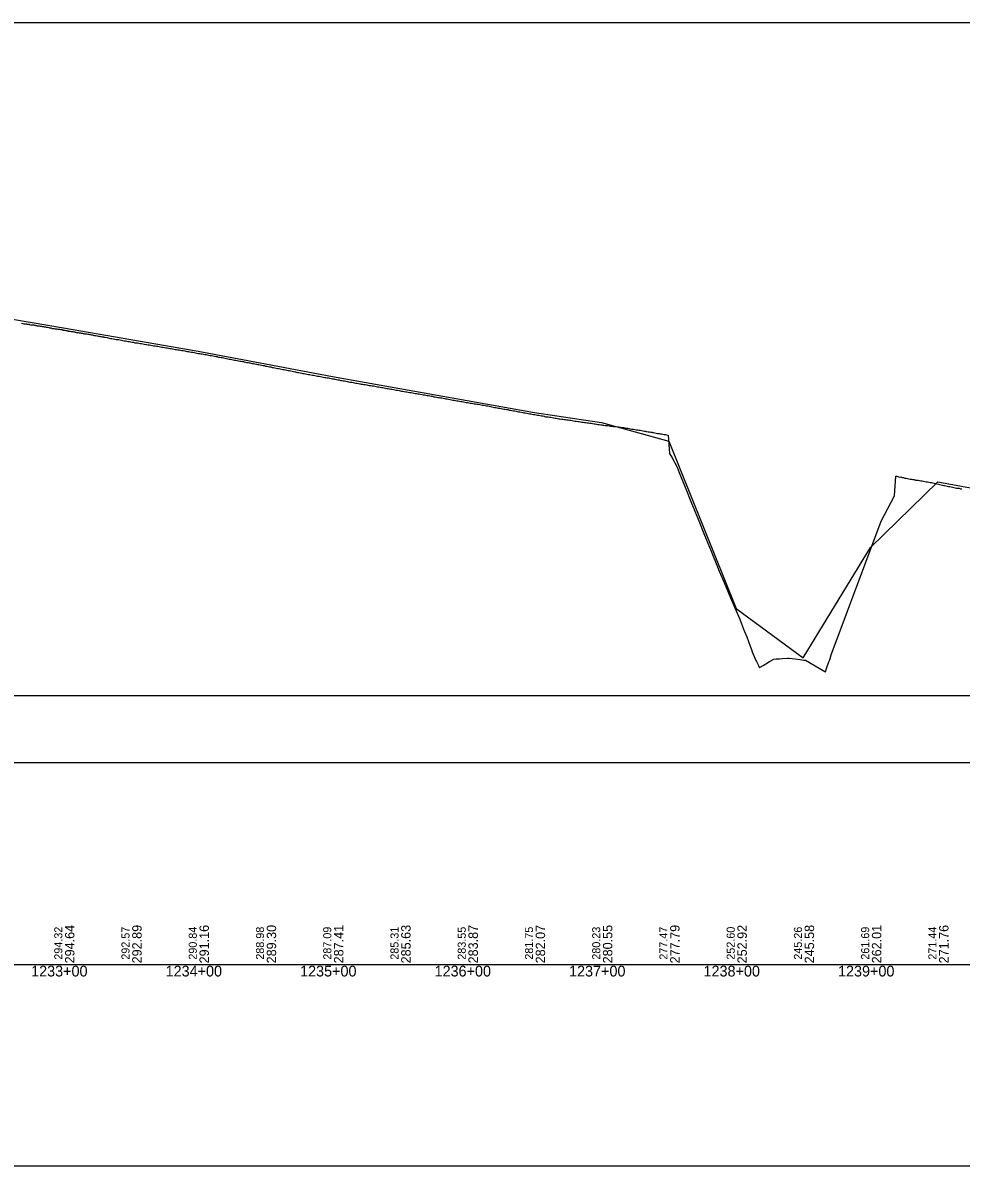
# Model space of a CAD drawing. Extents: x 2898 to 49495, y -15038 to -13538.
# Drawn here: x 12623 to 13321, y -15038 to -14188 of the extents above; entities that cross this region are included whole.
import ezdxf

# ---------------------------------------------------------------- set-up
doc = ezdxf.new("R2010")
doc.units = 0
for name, color, linetype in [('RD_DDB_Profile_EX', 7, 'Continuous'), ('RD_DDB_Profile_PR', 7, 'Continuous'), ('RD_DDB_StaTX', 7, 'Continuous'), ('RD_DDB_StripGrade', 7, 'Continuous'), ('RD_GPK_Profile_Cell', 7, 'Continuous'), ('RD_SHT_ShtClip', 7, 'Continuous')]:
    doc.layers.add(name, color=color, linetype=linetype)

msp = doc.modelspace()

# ---------------------------------------------------------------- linework, layer by layer
at = {"layer": 'RD_DDB_Profile_EX'}
for points in [[(12622.09, -14411.61), (12623.09, -14411.98), (12623.71, -14412.11), (12624.09, -14412.11), (12624.71, -14412.24), (12625.09, -14412.28), (12625.71, -14412.34), (12626.09, -14412.36), (12626.7, -14412.43), (12627.09, -14412.41), (12627.71, -14412.56), (12628.1, -14412.76), (12628.7, -14412.86), (12629.09, -14412.86), (12629.7, -14412.95), (12630.1, -14412.91), (12630.7, -14413.01), (12631.09, -14413.07), (12631.69, -14413.16), (12632.09, -14413.28), (12632.69, -14413.41), (12633.1, -14413.53), (12633.7, -14413.65), (12634.1, -14413.65), (12634.69, -14413.72), (12635.24, -14413.74), (12635.84, -14413.85), (12636.24, -14413.97), (12636.84, -14414.06), (12637.31, -14414.12), (12637.84, -14414.22), (12638.32, -14414.28), (12638.92, -14414.4), (12639.32, -14414.51), (12639.92, -14414.57), (12640.32, -14414.63), (12640.92, -14414.69), (12641.31, -14414.74), (12642.31, -14415.02), (12642.92, -14415.14), (12643.31, -14415.2), (12643.92, -14415.32), (12644.31, -14415.49), (12644.92, -14415.58), (12645.3, -14415.58), (12645.93, -14415.73), (12646.31, -14415.8), (12646.97, -14415.83), (12647.3, -14415.9), (12647.93, -14416.02), (12648.3, -14416.07), (12648.93, -14416.17), (12649.3, -14416.18), (12649.93, -14416.27), (12650.3, -14416.27), (12650.93, -14416.46), (12651.3, -14416.48), (12651.93, -14416.54), (12652.29, -14416.66), (12652.93, -14416.79), (12653.29, -14416.84), (12653.93, -14416.91), (12654.29, -14416.97), (12654.93, -14417.16), (12655.29, -14417.2), (12655.94, -14417.3), (12656.29, -14417.49), (12656.63, -14417.55), (12656.94, -14417.61), (12657.29, -14417.63), (12657.94, -14417.76), (12658.28, -14417.77), (12658.94, -14417.84), (12659.29, -14417.87), (12659.94, -14417.97), (12660.28, -14417.98), (12660.94, -14418.11), (12661.46, -14418.23), (12661.94, -14418.33), (12662.29, -14418.45), (12662.94, -14418.58), (12663.28, -14418.58), (12663.94, -14418.67), (12664.28, -14418.74), (12664.94, -14418.84), (12665.28, -14418.91), (12665.94, -14419.01), (12666.29, -14419.07), (12666.94, -14419.17), (12667.27, -14419.19)], [(12667.27, -14419.19), (12667.94, -14419.35), (12668.27, -14419.4), (12668.94, -14419.6), (12669.28, -14419.65), (12669.94, -14419.68), (12670.27, -14419.73), (12671.27, -14419.91), (12671.94, -14419.95), (12672.27, -14420), (12672.94, -14420.06), (12673.37, -14420.16), (12674.04, -14420.36), (12674.37, -14420.36), (12675.04, -14420.46), (12675.37, -14420.67), (12676.04, -14420.87), (12676.37, -14420.88), (12677.05, -14420.95), (12677.37, -14420.98), (12678.32, -14421.16), (12679.01, -14421.32), (12679.33, -14421.34), (12680.01, -14421.44), (12680.32, -14421.53), (12681.01, -14421.6), (12681.32, -14421.67), (12682.01, -14421.91), (12682.32, -14421.94), (12683.02, -14422.01), (12683.32, -14422.08), (12684.01, -14422.18), (12684.31, -14422.23), (12685.61, -14422.46), (12686.32, -14422.57), (12687.31, -14422.89), (12688.31, -14423.03), (12689.31, -14423.16), (12690.44, -14423.3), (12691.31, -14423.53), (12692.3, -14423.76), (12693.31, -14423.87), (12694.31, -14423.99), (12695.3, -14424.18), (12696.3, -14424.39), (12697.3, -14424.58), (12698.3, -14424.79), (12699.3, -14424.9), (12700.3, -14425.05), (12701.3, -14425.33), (12702.3, -14425.45), (12703.3, -14425.58), (12704.29, -14425.83), (12705.3, -14425.92), (12706.3, -14426.25), (12707.29, -14426.3), (12708.29, -14426.42), (12709.29, -14426.49), (12710.29, -14426.83), (12711.31, -14426.93), (12712.32, -14427.14), (12713.32, -14427.38), (12714.59, -14427.53), (12715.31, -14427.68), (12716.31, -14427.82), (12717.31, -14427.92), (12718.31, -14428.14), (12719.42, -14428.32), (12720.31, -14428.53), (12721.33, -14428.62), (12722.33, -14428.83), (12723.33, -14428.92), (12724.33, -14429.1), (12725.32, -14429.33), (12726.32, -14429.54), (12727.32, -14429.66), (12728.32, -14429.81), (12729.32, -14430.03), (12730.33, -14430.15), (12731.32, -14430.4), (12732.31, -14430.54), (12733.32, -14430.66), (12734.32, -14430.79), (12735.32, -14430.98), (12736.31, -14431.25), (12737.31, -14431.31), (12738.31, -14431.48), (12738.74, -14431.56), (12739.31, -14431.67), (12740.32, -14431.83), (12741.31, -14431.97), (12742.31, -14432.14), (12743.57, -14432.32), (12744.31, -14432.46), (12745.31, -14432.68), (12746.3, -14432.86), (12747.3, -14433.06), (12748.4, -14433.2), (12749.36, -14433.39), (12750.35, -14433.61), (12751.35, -14433.81)], [(12751.35, -14433.81), (12752.35, -14433.94), (12753.35, -14434.25), (12754.35, -14434.36), (12755.34, -14434.44), (12756.34, -14434.61), (12757.34, -14434.85), (12758.34, -14434.99), (12759.34, -14435.14), (12760.44, -14435.26), (12761.43, -14435.52), (12762.44, -14435.73), (12762.89, -14435.8), (12763.43, -14435.87), (12764.43, -14436.03), (12765.42, -14436.22), (12766.42, -14436.58), (12767.42, -14436.64), (12767.72, -14436.72), (12768.42, -14436.91), (12769.42, -14437.04), (12770.42, -14437.22), (12771.41, -14437.36), (12772.55, -14437.62), (12773.41, -14437.79), (12774.41, -14438.01), (12775.41, -14438.18), (12776.41, -14438.4), (12777.41, -14438.6), (12778.41, -14438.76), (12779.41, -14438.88), (12780.41, -14439.24), (12781.41, -14439.31), (12782.4, -14439.41), (12783.4, -14439.71), (12784.49, -14439.87), (12785.49, -14440.07), (12786.48, -14440.22), (12787.04, -14440.34), (12787.48, -14440.42), (12788.49, -14440.62), (12789.49, -14440.97), (12790.49, -14441.03), (12791.49, -14441.27), (12791.87, -14441.33), (12792.49, -14441.44), (12793.49, -14441.64), (12794.49, -14441.79), (12795.49, -14441.95), (12796.7, -14442.3), (12797.49, -14442.39), (12798.49, -14442.52), (12799.5, -14442.73), (12800.49, -14443), (12801.53, -14443.21), (12802.5, -14443.33), (12803.51, -14443.59), (12804.51, -14443.8), (12805.5, -14443.92), (12806.5, -14444.19), (12807.38, -14444.32), (12808.38, -14444.62), (12809.38, -14444.78), (12810.38, -14445.03), (12811.38, -14445.13), (12812.38, -14445.35), (12813.38, -14445.55), (12814.37, -14445.72), (12815.37, -14445.91), (12816.38, -14446.09), (12817.38, -14446.27), (12818.38, -14446.5), (12819.37, -14446.71), (12820.37, -14446.98), (12821.24, -14447.03), (12822.24, -14447.23), (12823.24, -14447.46), (12824.23, -14447.67), (12825.23, -14447.93), (12825.68, -14448.04), (12826.23, -14448.17), (12827.23, -14448.37), (12828.23, -14448.49), (12829.23, -14448.67), (12830.51, -14448.94), (12831.23, -14449.11), (12832.23, -14449.25), (12833.22, -14449.41), (12834.22, -14449.68), (12835.34, -14449.84), (12836.22, -14449.93), (12837.22, -14450.08), (12838.22, -14450.37), (12839.22, -14450.5), (12840.22, -14450.71), (12841.21, -14450.84), (12842.22, -14451.05), (12843.29, -14451.22), (12844.3, -14451.44), (12845.29, -14451.61), (12846.29, -14451.78)], [(12846.29, -14451.78), (12847.29, -14452.05), (12848.29, -14452.09), (12849.29, -14452.33), (12850.29, -14452.48), (12851.29, -14452.66), (12852.29, -14452.87), (12853.29, -14453.02), (12854.29, -14453.23), (12854.66, -14453.29), (12855.3, -14453.4), (12856.29, -14453.63), (12857.29, -14453.82), (12858.29, -14453.96), (12859.49, -14454.25), (12860.29, -14454.38), (12861.29, -14454.55), (12862.29, -14454.7), (12863.3, -14454.94), (12864.32, -14455.16), (12865.3, -14455.32), (12866.29, -14455.51), (12866.62, -14455.55), (12867.62, -14455.72), (12868.62, -14455.9), (12869.62, -14456.05), (12870.61, -14456.23), (12871.61, -14456.45), (12872.61, -14456.59), (12873.61, -14456.82), (12873.98, -14456.87), (12874.61, -14456.99), (12875.61, -14457.12), (12876.61, -14457.34), (12877.61, -14457.43), (12878.81, -14457.66), (12879.61, -14457.85), (12880.6, -14458.02), (12881.67, -14458.15), (12882.67, -14458.29), (12883.67, -14458.43), (12884.67, -14458.64), (12885.67, -14458.82), (12886.67, -14458.98), (12887.66, -14459.17), (12888.66, -14459.33), (12889.66, -14459.52), (12890.66, -14459.68), (12891.66, -14459.89), (12892.66, -14460.04), (12893.66, -14460.19), (12894.66, -14460.43), (12895.66, -14460.53), (12896.66, -14460.7), (12897.66, -14460.92), (12898.66, -14461.17), (12899.66, -14461.3), (12900.66, -14461.53), (12901.66, -14461.64), (12902.96, -14461.86), (12903.67, -14461.99), (12904.66, -14462.18), (12905.66, -14462.4), (12906.66, -14462.55), (12907.79, -14462.7), (12908.67, -14462.83), (12909.66, -14463.02), (12910.67, -14463.22), (12911.66, -14463.4), (12912.67, -14463.57), (12913.67, -14463.76), (12914.67, -14463.91), (12915.67, -14464.09), (12916.64, -14464.26), (12917.63, -14464.37), (12918.63, -14464.59), (12919.63, -14464.82), (12920.63, -14464.94), (12921.62, -14465.14), (12922.62, -14465.26), (12923.62, -14465.42), (12924.62, -14465.62), (12925.62, -14465.77), (12926.62, -14466.02), (12927.61, -14466.11), (12928.62, -14466.38), (12929.61, -14466.55), (12930.61, -14466.82), (12931.61, -14466.89), (12931.94, -14466.94), (12932.61, -14467.06), (12933.61, -14467.22), (12934.61, -14467.31), (12935.61, -14467.57), (12936.77, -14467.77), (12937.58, -14467.95), (12938.58, -14468.1), (12939.58, -14468.29), (12940.74, -14468.51), (12941.74, -14468.69), (12942.73, -14468.92)], [(12942.73, -14468.92), (12943.73, -14469.07), (12944.73, -14469.2), (12945.73, -14469.36), (12946.73, -14469.47), (12947.73, -14469.69), (12948.73, -14469.9), (12949.73, -14470.04), (12950.73, -14470.26), (12951.73, -14470.42), (12952.72, -14470.61), (12953.73, -14470.79), (12954.73, -14470.94), (12955.72, -14471.11), (12956.09, -14471.2), (12956.73, -14471.32), (12957.72, -14471.5), (12958.72, -14471.63), (12959.72, -14471.82), (12960.92, -14471.99), (12961.72, -14472.06), (12962.72, -14472.27), (12963.72, -14472.5), (12964.72, -14472.67), (12965.75, -14472.82), (12966.72, -14472.99), (12967.72, -14473.15), (12968.71, -14473.31), (12969.72, -14473.5), (12970.72, -14473.68), (12971.71, -14473.9), (12972.72, -14474.1), (12973.72, -14474.37), (12974.7, -14474.52), (12975.7, -14474.67), (12976.7, -14474.88), (12977.7, -14475.01), (12978.7, -14475.2), (12979.7, -14475.38), (12980.7, -14475.56), (12981.69, -14475.67), (12982.7, -14475.87), (12983.69, -14476.03), (12984.69, -14476.34), (12985.07, -14476.37), (12985.69, -14476.42), (12986.69, -14476.63), (12987.69, -14476.8), (12988.69, -14477), (12989.9, -14477.2), (12990.69, -14477.32), (12991.67, -14477.61), (12992.67, -14477.69), (12993.67, -14477.99), (12994.73, -14478.12), (12995.67, -14478.33), (12996.67, -14478.5), (12997.67, -14478.65), (12998.67, -14478.93), (12999.67, -14479.04), (13000.67, -14479.12), (13001.67, -14479.35), (13002.66, -14479.55), (13003.67, -14479.76), (13004.67, -14479.85), (13005.66, -14480.04), (13006.66, -14480.24), (13007.67, -14480.46), (13008.66, -14480.55), (13009.61, -14480.71), (13010.6, -14480.92), (13011.6, -14481.31), (13012.6, -14481.33), (13013.59, -14481.46), (13014.59, -14481.64), (13015.59, -14481.73), (13016.59, -14481.94), (13017.59, -14482.03), (13018.89, -14482.29), (13019.59, -14482.36), (13020.59, -14482.54), (13021.59, -14482.76), (13022.58, -14482.86), (13023.72, -14483.02), (13024.58, -14483.17), (13025.58, -14483.26), (13026.58, -14483.41), (13027.58, -14483.61), (13028.58, -14483.72), (13029.58, -14483.85), (13030.58, -14483.94), (13031.58, -14484.12), (13032.58, -14484.31), (13033.58, -14484.49), (13034.58, -14484.7), (13035.69, -14484.84), (13036.68, -14484.96), (13037.68, -14485.02), (13038.68, -14485.26), (13039.68, -14485.33), (13040.68, -14485.5)], [(13040.68, -14485.5), (13041.68, -14485.58), (13042.68, -14485.78), (13043.04, -14485.8), (13043.68, -14485.86), (13044.68, -14486.08), (13045.68, -14486.19), (13046.68, -14486.32), (13047.87, -14486.48), (13048.68, -14486.62), (13049.68, -14486.77), (13050.68, -14486.96), (13051.67, -14487.07), (13052.7, -14487.21), (13053.67, -14487.33), (13054.42, -14487.45), (13055.03, -14487.58), (13056.03, -14487.75), (13057.03, -14487.83), (13058.02, -14487.89), (13059.03, -14488.15), (13060.02, -14488.26), (13061.02, -14488.32), (13062.02, -14488.44), (13062.36, -14488.47), (13063.01, -14488.53), (13064.02, -14488.67), (13065.01, -14488.79), (13066.01, -14488.92), (13067.19, -14489.07), (13068, -14489.24), (13069.01, -14489.4), (13070, -14489.42), (13071, -14489.47), (13072.02, -14489.74), (13072.99, -14489.88), (13073.99, -14490.01), (13074.99, -14490.26), (13075.98, -14490.48), (13076.99, -14490.6), (13077.98, -14490.78), (13078.98, -14490.94), (13079.97, -14491.06), (13080.97, -14491.22), (13081.97, -14491.41), (13082.97, -14491.61), (13083.96, -14491.79), (13084.96, -14491.99), (13085.96, -14492.12), (13086.51, -14492.25), (13086.95, -14492.32), (13087.96, -14492.42), (13088.96, -14492.49), (13089.95, -14492.68), (13090.95, -14492.88), (13091.34, -14492.96), (13091.94, -14493.11), (13092.95, -14493.32), (13093.95, -14493.47), (13094.94, -14493.66), (13096.17, -14493.77), (13096.94, -14493.92), (13097.93, -14494.07), (13098.94, -14494.22), (13099.93, -14494.44), (13101, -14494.56), (13101.93, -14494.67), (13102.93, -14495), (13103.93, -14508.53), (13105.83, -14511.96), (13109.56, -14518.74), (13110.66, -14521.6), (13112.47, -14526.36), (13115.49, -14533.75), (13120.32, -14545.6), (13125.15, -14557.45), (13129.98, -14569.29), (13134.81, -14581.13), (13139.64, -14592.97), (13140.89, -14596.04), (13144.47, -14604.47), (13149.3, -14615.86), (13154.13, -14627.24), (13156.12, -14631.92), (13158.96, -14639.2), (13160.34, -14642.73), (13161.28, -14644.99), (13163.79, -14651.79), (13164.73, -14654.33), (13165.39, -14656.12), (13166.12, -14657.8), (13166.91, -14659.57), (13167.97, -14662.53), (13168.62, -14663.16), (13169.28, -14664.85), (13170.04, -14666.34), (13170.81, -14667.87), (13171.36, -14667.54), (13173.45, -14666.25), (13175.48, -14665), (13178.28, -14663.36)], [(13178.28, -14663.36), (13178.64, -14663.15), (13179.76, -14662.44), (13181.43, -14661.52), (13183.11, -14661.41), (13185.56, -14661.26), (13187.94, -14661.08), (13191.5, -14660.81), (13192.28, -14660.76), (13192.83, -14660.72), (13197.32, -14661.32), (13201.08, -14661.82), (13202.25, -14661.97), (13203.81, -14662.24), (13204.94, -14662.29), (13219.41, -14670.67), (13219.8, -14670.87), (13220.6, -14668.54), (13220.92, -14667.67), (13222.32, -14663.52), (13222.99, -14661.93), (13224.19, -14658.43), (13261.24, -14558.9), (13271.1, -14540.08), (13272.21, -14525.46), (13272.87, -14525.56), (13274.78, -14526.31), (13275.79, -14526.1), (13276.79, -14526.39), (13277.8, -14526.54), (13278.8, -14526.89), (13279.79, -14526.9), (13280.79, -14527.19), (13281.8, -14527.45), (13282.79, -14527.64), (13283.79, -14527.79), (13284.79, -14527.92), (13285.79, -14528.02), (13286.8, -14528.35), (13287.79, -14528.46), (13288.79, -14528.57), (13289.79, -14528.68), (13290.79, -14528.92), (13291.79, -14529.07), (13292.78, -14529.32), (13293.79, -14529.47), (13294.79, -14529.62), (13295.79, -14529.77), (13296.79, -14530.07), (13297.78, -14530.21), (13298.78, -14530.28), (13299.79, -14530.44), (13300.78, -14530.67), (13301.78, -14530.91), (13302.78, -14531.11), (13303.78, -14531.35), (13304.79, -14531.79), (13305.78, -14531.85), (13306.78, -14532.19), (13307.78, -14532.43), (13308.32, -14532.45), (13309.32, -14532.6), (13310.32, -14532.89), (13311.32, -14533.05), (13312.32, -14533.2), (13313.32, -14533.54), (13314.32, -14533.63), (13315.32, -14533.84), (13316.32, -14534.13), (13317.32, -14534.38), (13318.32, -14534.48), (13319.31, -14534.53), (13320.31, -14534.82), (13321.31, -14535)]]:
    msp.add_lwpolyline(points, dxfattribs=at)
at = {"layer": 'RD_DDB_Profile_PR'}
msp.add_lwpolyline([(12603.38, -14406.9), (12653.38, -14415.25), (12703.38, -14424), (12753.38, -14432.65), (12803.38, -14441.96), (12853.38, -14451.44), (12903.38, -14460.34), (12953.38, -14469.13), (13003.38, -14478.1), (13053.38, -14485.7), (13103.38, -14499.49), (13153.38, -14623.88), (13203.38, -14660.57), (13253.38, -14578.42), (13303.38, -14529.66), (13353.38, -14538.87)], dxfattribs=at)
at = {"layer": 'RD_GPK_Profile_Cell'}
msp.add_line((2976.05, -14888.47), (48721.13, -14888.47), dxfattribs=at)
at = {"layer": 'RD_SHT_ShtClip'}
for points in [[(13476.22, -14688.47), (13476.22, -14188.47), (13476.22, -14188.47), (11976.38, -14188.47), (11976.38, -14688.47)], [(11956.38, -14738.47), (13496.05, -14738.47), (13496.05, -15038.47), (11956.38, -15038.47)]]:
    msp.add_lwpolyline(points, close=True, dxfattribs=at)

# ---------------------------------------------------------------- texts
at = {"layer": 'RD_DDB_StaTX'}
for s, p in [('1233+00', (12629.18, -14897.47)), ('1234+00', (12729.18, -14897.47)), ('1235+00', (12829.18, -14897.47)), ('1236+00', (12929.18, -14897.47)), ('1237+00', (13029.18, -14897.47)), ('1238+00', (13129.18, -14897.47)), ('1239+00', (13229.18, -14897.47))]:
    msp.add_text(s, height=8, dxfattribs=at).set_placement(p)
at = {"layer": 'RD_DDB_StripGrade'}
for s, height, p in [('294.32', 6, (12652.38, -14884.98)), ('294.64', 7, (12661.38, -14887.72)), ('292.57', 6, (12702.38, -14884.98)), ('292.89', 7, (12711.38, -14887.72)), ('290.84', 6, (12752.38, -14884.98)), ('291.16', 7, (12761.38, -14887.72)), ('288.98', 6, (12802.38, -14884.98)), ('289.30', 7, (12811.38, -14887.72)), ('287.09', 6, (12852.38, -14884.98)), ('287.41', 7, (12861.38, -14887.72)), ('285.31', 6, (12902.38, -14884.98)), ('285.63', 7, (12911.38, -14887.72)), ('283.55', 6, (12952.38, -14884.98)), ('283.87', 7, (12961.38, -14887.72)), ('281.75', 6, (13002.38, -14884.98)), ('282.07', 7, (13011.38, -14887.72)), ('280.23', 6, (13052.38, -14884.98)), ('280.55', 7, (13061.38, -14887.72)), ('277.47', 6, (13102.38, -14884.98)), ('277.79', 7, (13111.38, -14887.72)), ('252.60', 6, (13152.38, -14884.98)), ('252.92', 7, (13161.38, -14887.72)), ('245.26', 6, (13202.38, -14884.98)), ('245.58', 7, (13211.38, -14887.72)), ('261.69', 6, (13252.38, -14884.98)), ('262.01', 7, (13261.38, -14887.72)), ('271.44', 6, (13302.38, -14884.98)), ('271.76', 7, (13311.38, -14887.72))]:
    msp.add_text(s, height=height, rotation=90, dxfattribs=at).set_placement(p)

doc.saveas('drawing.dxf')
